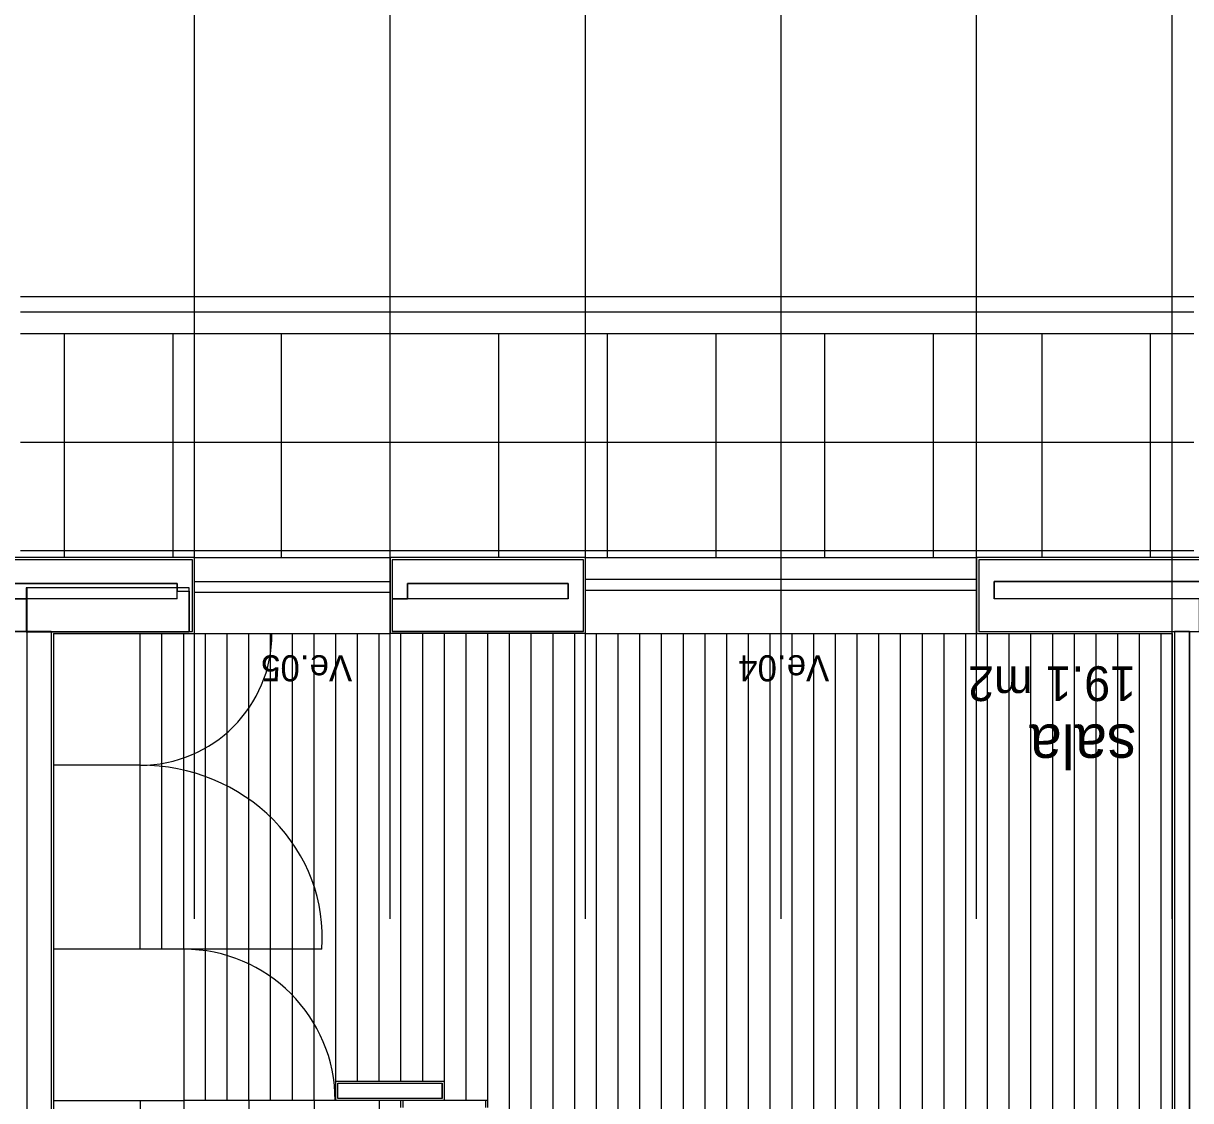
# Model space of a CAD drawing. Extents: x 1248 to 1356, y -443 to -224.
# Drawn here: x 1340.11 to 1345.48, y -234.42 to -229.47 of the extents above; entities that cross this region are included whole.
import ezdxf

# ---------------------------------------------------------------- set-up
doc = ezdxf.new("R2010")
doc.units = 0
for name, color, linetype in [('corte', 7, 'Continuous'), ('estereoctomias', 7, 'Continuous'), ('Level 1', 7, 'Continuous'), ('Level 10', 7, 'Continuous'), ('Level 13', 7, 'Continuous'), ('Level 2', 7, 'Continuous'), ('Level 3', 7, 'Continuous'), ('Level 4', 7, 'Continuous'), ('Level 40', 7, 'Continuous'), ('Level 60', 7, 'Continuous'), ('revestimentos', 7, 'Continuous'), ('vermelhos-tracej', 7, 'Continuous')]:
    doc.layers.add(name, color=color, linetype=linetype)

msp = doc.modelspace()

# ---------------------------------------------------------------- linework, layer by layer
at = {"layer": 'corte'}
for p, q in [((1340.884, -231.934), (1339.1033, -231.934)), ((1342.684, -231.934), (1341.804, -231.934)), ((1340.814, -232.044), (1339.1733, -232.044)), ((1340.124, -238.544), (1340.124, -232.0639)), ((1342.614, -232.044), (1341.874, -232.044)), ((1346.2137, -232.034), (1344.574, -232.034)), ((1339.1733, -232.114), (1340.1183, -232.114)), ((1340.814, -232.114), (1340.124, -232.114)), ((1342.614, -232.114), (1341.874, -232.114)), ((1345.519, -232.114), (1344.574, -232.114)), ((1340.234, -232.264), (1339.1033, -232.264)), ((1342.684, -232.264), (1341.804, -232.264))]:
    msp.add_line(p, q, dxfattribs=at)
msp.add_lwpolyline([(1340.8683, -232.0639), (1340.1183, -232.0639), (1340.1183, -232.2657), (1340.8683, -232.2657)], close=True, dxfattribs=at)
at = {"layer": 'estereoctomias'}
for points in [[(1340.884, -232.264), (1340.884, -231.934), (1339.1033, -231.934), (1339.1033, -232.264), (1340.124, -232.264), (1340.124, -232.114), (1339.1733, -232.114), (1339.1733, -232.044), (1340.814, -232.044), (1340.814, -232.079), (1340.8683, -232.079), (1340.8683, -232.2657)], [(1342.684, -232.264), (1342.684, -231.934), (1341.804, -231.934), (1341.804, -232.114), (1341.874, -232.114), (1341.874, -232.044), (1342.614, -232.044), (1342.614, -232.114), (1341.804, -232.114), (1341.804, -232.264)], [(1346.2837, -232.264), (1346.2837, -231.934), (1344.504, -231.934), (1344.504, -232.264), (1345.519, -232.264), (1345.519, -232.114), (1344.574, -232.114), (1344.574, -232.034), (1346.2137, -232.034), (1346.2137, -232.074), (1346.2137, -232.0639), (1346.269, -232.0639), (1346.269, -232.264)], [(1340.234, -232.264), (1340.234, -235.8713), (1340.124, -235.8713), (1340.124, -232.2657)], [(1345.474, -235.8713), (1345.474, -232.264), (1345.404, -232.264), (1345.404, -235.8713)], [(1342.034, -234.344), (1342.034, -234.414), (1341.554, -234.414), (1341.554, -234.344)]]:
    msp.add_lwpolyline(points, close=True, dxfattribs=at)
at = {"layer": 'Level 1'}
for p, q in [((1340.884, -232.264), (1340.884, -231.934)), ((1341.804, -231.934), (1341.804, -232.264)), ((1342.684, -232.264), (1342.684, -231.934)), ((1344.504, -231.934), (1344.504, -232.264)), ((1346.2837, -231.934), (1344.504, -231.934)), ((1340.814, -232.114), (1340.814, -232.044)), ((1341.874, -232.044), (1341.874, -232.114)), ((1342.614, -232.114), (1342.614, -232.044)), ((1344.574, -232.034), (1344.574, -232.114)), ((1340.124, -232.114), (1340.124, -232.114)), ((1340.234, -232.264), (1340.884, -232.264)), ((1340.234, -232.264), (1340.234, -238.544)), ((1344.504, -232.264), (1345.6337, -232.264)), ((1345.404, -232.264), (1345.404, -238.424)), ((1345.474, -232.264), (1345.474, -238.494)), ((1341.554, -234.414), (1341.554, -234.344)), ((1341.554, -234.344), (1342.034, -234.344)), ((1342.034, -234.414), (1342.034, -234.344)), ((1342.244, -234.424), (1341.544, -234.424)), ((1342.034, -234.414), (1341.554, -234.414)), ((1341.844, -234.456), (1341.844, -234.424)), ((1341.854, -234.456), (1341.854, -234.424)), ((1342.234, -234.456), (1342.234, -234.424)), ((1342.244, -234.456), (1342.244, -234.424))]:
    msp.add_line(p, q, dxfattribs=at)
at = {"layer": 'Level 10'}
for p, q in [((1345.4933, -230.894), (1340.0933, -230.894)), ((1340.2933, -230.894), (1340.2933, -231.924)), ((1340.7933, -230.894), (1340.7933, -231.924)), ((1341.2933, -230.894), (1341.2933, -231.924)), ((1341.7933, -230.894), (1341.7933, -231.924)), ((1342.2933, -230.894), (1342.2933, -231.924)), ((1342.7933, -230.894), (1342.7933, -231.924)), ((1343.2933, -230.894), (1343.2933, -231.924)), ((1343.7933, -230.894), (1343.7933, -231.924)), ((1344.2933, -230.894), (1344.2933, -231.924)), ((1344.7933, -230.894), (1344.7933, -231.924)), ((1345.2933, -230.894), (1345.2933, -231.924)), ((1345.4933, -231.394), (1340.0933, -231.394)), ((1345.4933, -231.894), (1340.0933, -231.894)), ((1340.744, -233.727), (1340.744, -232.274)), ((1340.844, -233.727), (1340.844, -232.274)), ((1340.944, -234.424), (1340.944, -232.274)), ((1341.044, -234.424), (1341.044, -232.274)), ((1341.144, -234.424), (1341.144, -232.274)), ((1341.244, -234.424), (1341.244, -232.274)), ((1341.344, -234.424), (1341.344, -232.274)), ((1341.444, -234.424), (1341.444, -232.274)), ((1341.544, -234.334), (1341.544, -232.274)), ((1341.644, -234.334), (1341.644, -232.274)), ((1341.744, -234.334), (1341.744, -232.274)), ((1341.844, -234.334), (1341.844, -232.274)), ((1341.944, -234.334), (1341.944, -232.274)), ((1342.044, -234.334), (1342.044, -232.274)), ((1342.144, -234.424), (1342.144, -232.274)), ((1342.244, -234.424), (1342.244, -232.274)), ((1342.344, -238.414), (1342.344, -232.274)), ((1342.444, -238.414), (1342.444, -232.274)), ((1342.544, -238.414), (1342.544, -232.274)), ((1342.644, -238.414), (1342.644, -232.274)), ((1342.744, -238.414), (1342.744, -232.274)), ((1342.844, -238.414), (1342.844, -232.274)), ((1342.944, -236.624), (1342.944, -232.274)), ((1343.044, -236.624), (1343.044, -232.274)), ((1343.144, -236.624), (1343.144, -232.274)), ((1343.244, -236.624), (1343.244, -232.274)), ((1343.344, -236.624), (1343.344, -232.274)), ((1343.444, -236.624), (1343.444, -232.274)), ((1343.544, -236.624), (1343.544, -232.274)), ((1343.644, -236.624), (1343.644, -232.274)), ((1343.744, -236.624), (1343.744, -232.274)), ((1343.844, -236.624), (1343.844, -232.274)), ((1343.944, -236.624), (1343.944, -232.274)), ((1344.044, -236.624), (1344.044, -232.274)), ((1344.144, -236.624), (1344.144, -232.274)), ((1344.244, -236.624), (1344.244, -232.274)), ((1344.344, -236.624), (1344.344, -232.274)), ((1344.444, -236.624), (1344.444, -232.274)), ((1344.544, -236.624), (1344.544, -232.274)), ((1344.644, -236.624), (1344.644, -232.274)), ((1344.744, -236.624), (1344.744, -232.274)), ((1344.844, -236.624), (1344.844, -232.274)), ((1344.944, -236.624), (1344.944, -232.274)), ((1345.044, -236.624), (1345.044, -232.274)), ((1345.144, -236.624), (1345.144, -232.274)), ((1345.244, -236.624), (1345.244, -232.274)), ((1345.344, -236.624), (1345.344, -232.274)), ((1341.544, -234.424), (1340.847, -234.424)), ((1341.144, -234.424), (1341.144, -236.824)), ((1341.444, -234.424), (1341.444, -236.824)), ((1341.744, -234.424), (1341.744, -236.824))]:
    msp.add_line(p, q, dxfattribs=at)
at = {"layer": 'Level 13'}
for p, q in [((1340.644, -233.727), (1340.644, -232.274)), ((1340.844, -233.727), (1340.244, -233.727)), ((1340.844, -233.727), (1340.844, -236.824))]:
    msp.add_line(p, q, dxfattribs=at)
at = {"layer": 'Level 2'}
for p, q in [((1345.4933, -230.724), (1340.0933, -230.724)), ((1345.4933, -230.794), (1340.0933, -230.794)), ((1340.894, -231.924), (1341.794, -231.924)), ((1342.694, -231.924), (1344.494, -231.924)), ((1340.894, -232.034), (1341.794, -232.034)), ((1342.694, -232.024), (1344.494, -232.024)), ((1340.894, -232.084), (1341.794, -232.084)), ((1342.694, -232.074), (1344.494, -232.074)), ((1340.894, -232.274), (1341.794, -232.274)), ((1342.694, -232.274), (1344.494, -232.274))]:
    msp.add_line(p, q, dxfattribs=at)
at = {"layer": 'Level 3'}
for q in [(1340.644, -235.634), (1340.844, -234.424)]:
    msp.add_line((1340.644, -234.424), q, dxfattribs=at)
at = {"layer": 'Level 4'}
for p, q in [((1340.644, -232.88), (1340.244, -232.88)), ((1341.4791, -233.727), (1340.644, -233.727)), ((1340.244, -234.424), (1340.644, -234.424))]:
    msp.add_line(p, q, dxfattribs=at)
for centre, radius, start, end in [((1340.644, -232.274), 0.606, 270, 0), ((1340.844, -234.424), 0.697, 0, 90)]:
    msp.add_arc(centre, radius, start, end, dxfattribs=at)
msp.add_ellipse((1340.644, -233.6703), major_axis=(-0.8372, 0), ratio=0.943954, start_param=3.069792, end_param=4.712389, dxfattribs=at)
at = {"layer": 'revestimentos'}
for p, q in [((1340.894, -231.924), (1339.0933, -231.924)), ((1340.894, -232.274), (1340.894, -231.924)), ((1341.794, -231.924), (1341.794, -232.274)), ((1342.694, -231.924), (1341.794, -231.924)), ((1342.694, -232.274), (1342.694, -231.924)), ((1344.494, -231.924), (1344.494, -232.274)), ((1346.2937, -231.924), (1344.494, -231.924)), ((1340.244, -232.274), (1340.244, -236.824)), ((1340.244, -232.274), (1340.894, -232.274)), ((1342.694, -232.274), (1341.794, -232.274)), ((1344.494, -232.274), (1345.394, -232.274)), ((1345.394, -232.274), (1345.394, -238.414)), ((1341.544, -234.334), (1342.044, -234.334)), ((1341.544, -234.424), (1341.544, -234.334)), ((1342.044, -234.424), (1342.044, -234.334))]:
    msp.add_line(p, q, dxfattribs=at)
at = {"layer": 'vermelhos-tracej'}
for p, q in [((1340.894, -233.587), (1340.894, -228.3936)), ((1341.794, -233.587), (1341.794, -228.3936)), ((1342.694, -233.587), (1342.694, -228.3936)), ((1343.594, -233.587), (1343.594, -228.3936)), ((1344.494, -233.587), (1344.494, -228.3936)), ((1345.394, -233.587), (1345.394, -228.3936))]:
    msp.add_line(p, q, dxfattribs=at)

# ---------------------------------------------------------------- texts
at = {"layer": 'Level 40'}
for s, p in [('Ve.05', (1341.6194, -232.3738)), ('Ve.04', (1343.8155, -232.3738))]:
    msp.add_text(s, height=0.12, rotation=180, dxfattribs=at).set_placement(p)
at = {"layer": 'Level 60'}
for s, height, p in [('19.1 m2', 0.16, (1345.2276, -232.4246)), ('sala', 0.2, (1345.2276, -232.6924))]:
    msp.add_text(s, height=height, rotation=180, dxfattribs=at).set_placement(p)

doc.saveas('drawing.dxf')
